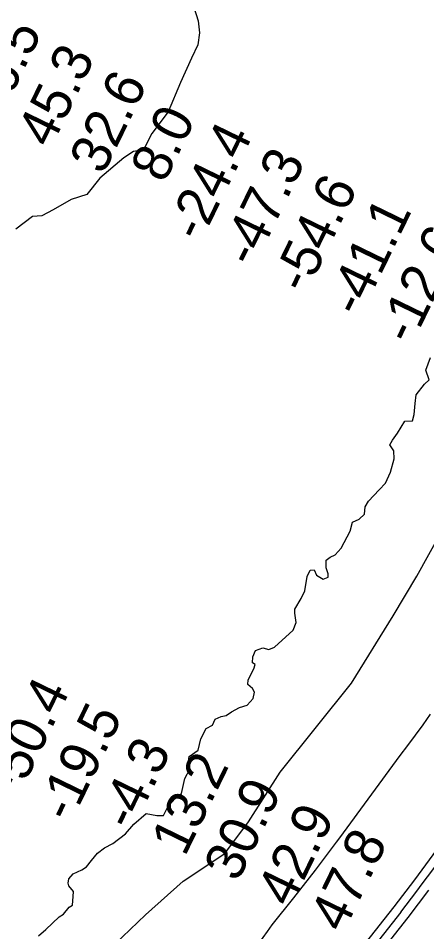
# Model space of a CAD drawing. Extents: x 3180038 to 3217926, y 922069 to 947485.
# Drawn here: x 3188541 to 3189237, y 935201 to 936760 of the extents above; entities that cross this region are included whole.
import ezdxf

# ---------------------------------------------------------------- set-up
doc = ezdxf.new("R2010")
doc.units = 0
for name, color, linetype in [('V-LEVE-TOET', 7, 'Continuous'), ('V-RIVR-EDGE', 7, 'Continuous'), ('V-RIVR-RANG', 7, 'Continuous'), ('V-ROAD-CNTR', 7, 'Continuous'), ('V-TOPO-SHOR', 7, 'Continuous')]:
    doc.layers.add(name, color=color, linetype=linetype)

msp = doc.modelspace()

# ---------------------------------------------------------------- linework, layer by layer
at = {"layer": 'V-LEVE-TOET'}
msp.add_lwpolyline([(3188950.6, 935180.6), (3188965.4, 935201.4), (3188973.1, 935212.6), (3188973.1, 935212.6), (3189010.5, 935259), (3189047.1, 935306), (3189082.9, 935353.6), (3189088.6, 935361.3), (3189088.6, 935361.3), (3189191.3, 935501.6), (3189191.3, 935501.6), (3189204.7, 935519), (3189217.8, 935536.5), (3189230.6, 935554.3), (3189243.1, 935572.3)], dxfattribs=at)
at = {"layer": 'V-RIVR-EDGE'}
for points in [[(3188839.8, 936778.5), (3188847, 936755.1)], [(3188847, 936755.1), (3188849.6, 936734.9), (3188846.4, 936714.7), (3188836, 936691.4), (3188817.2, 936649.9), (3188796.3, 936600.2), (3188768.2, 936562.9), (3188754.2, 936535), (3188737, 936532.4), (3188720.4, 936521.6), (3188679.4, 936486.9), (3188657.5, 936459), (3188630.5, 936450.7), (3188599.9, 936432.7), (3188580.7, 936422.8), (3188565.1, 936421.3), (3188536.5, 936399.6)], [(3188758.4, 935402.5), (3188776.5, 935399.4), (3188788.4, 935399.3), (3188796.3, 935415.4), (3188808.2, 935428.3), (3188819.1, 935437.1), (3188824.4, 935462.5), (3188833.2, 935478.1), (3188830.1, 935488.4), (3188831.7, 935499.9), (3188847.3, 935510.7), (3188852, 935529.9), (3188860.9, 935547.5), (3188871.8, 935553.2), (3188876, 935563.5), (3188886.4, 935568.2), (3188895.2, 935569.7), (3188904, 935576.4), (3188917.5, 935583.7), (3188930.5, 935587.8), (3188940.9, 935599.2), (3188943.5, 935610), (3188939.9, 935616.3), (3188931.6, 935623), (3188932.2, 935630.8), (3188942.1, 935649.5), (3188944.1, 935656.7), (3188940, 935659.8), (3188940.5, 935670.2), (3188944.7, 935680.6), (3188957.2, 935685.2), (3188967.5, 935682.6), (3188977.4, 935686.7), (3189009.1, 935715.7), (3189014.3, 935728.6), (3189011.8, 935744.7), (3189011.8, 935751.5), (3189022.7, 935769.6), (3189029, 935782.5), (3189033.2, 935806.9), (3189038.4, 935817.8), (3189045.2, 935818.8), (3189048.8, 935809.5), (3189060.2, 935802.7), (3189069, 935805.8), (3189069, 935811.5), (3189065.4, 935821.9), (3189065.4, 935835.3), (3189072.2, 935840), (3189081, 935844.1), (3189090.9, 935855.5), (3189106.5, 935884.5), (3189110.2, 935900.1), (3189121.6, 935905.2), (3189131, 935913.5), (3189132, 935925.9), (3189137.8, 935935.8), (3189146.6, 935945.6), (3189156, 935954.9), (3189166.4, 935966.3), (3189175.2, 935985), (3189181.5, 936007.8), (3189180.5, 936021.8), (3189173.8, 936031.6), (3189178.5, 936039.9), (3189186.8, 936051.8), (3189199.3, 936072), (3189212.3, 936073), (3189215.4, 936083.4), (3189217, 936102.6), (3189218.6, 936117.1), (3189233.2, 936135.2), (3189241, 936143), (3189235.3, 936159.1), (3189243.1, 936180.8)], [(3188575.3, 935194), (3188587.8, 935204.8), (3188610.1, 935226.6), (3188617.9, 935231.2), (3188627.3, 935243.1), (3188633, 935246.2), (3188634.1, 935261.3), (3188634.6, 935269.6), (3188626.8, 935279.4), (3188625.8, 935284.1), (3188626.9, 935291.4), (3188634.2, 935299.6), (3188648.7, 935306.3), (3188657, 935311.5), (3188665.3, 935322.4), (3188675.7, 935334.8), (3188687.7, 935344.1), (3188701.7, 935351.8), (3188723.5, 935367.9), (3188737.6, 935384.4), (3188758.4, 935402.5)]]:
    msp.add_lwpolyline(points, dxfattribs=at)
at = {"layer": 'V-ROAD-CNTR'}
for points in [[(3191151.8, 939057.1), (3189829.7, 936317.7), (3189780.6, 936216.3), (3189729.6, 936116.7), (3189676.7, 936017.8), (3189622.4, 935919), (3189566.1, 935821.9), (3189508.3, 935726.2), (3189454.5, 935639.5), (3189409.3, 935567.6), (3189362.7, 935497.1), (3189314.9, 935427.3), (3189266, 935357.7), (3189215.7, 935289.5), (3189180.7, 935243.5), (3188970.6, 934976.4)], [(3189239.7, 935271.6), (3189204.5, 935225.2), (3188985.5, 934946.7)], [(3189192.6, 935234.3), (3188973.6, 934955.8)]]:
    msp.add_lwpolyline(points, dxfattribs=at)
msp.add_arc((3185329.5, 938198.4), 4869.2, 322.5019, 328.187, dxfattribs=at)
at = {"layer": 'V-TOPO-SHOR'}
msp.add_lwpolyline([(3188341.8, 934753.7), (3188666.1, 935142.1), (3188757.3, 935230), (3188821.5, 935287.4), (3188892.4, 935334.7), (3188933, 935388.7), (3188987, 935473.2), (3189108.6, 935625.2), (3189179.6, 935740), (3189220.1, 935807.6), (3189260.6, 935881.9), (3189277.5, 935929.2), (3189297.8, 935986.6), (3189345.1, 936121.7), (3189493.7, 936331.2), (3189730.2, 936824.4)], dxfattribs=at)

# ---------------------------------------------------------------- texts
at = {"layer": 'V-RIVR-RANG'}
for s, p in [('46.5', (3188505.9, 936579.6)), ('45.3', (3188595.9, 936536.1)), ('32.6', (3188685.2, 936491)), ('8.0', (3188789.3, 936476.4)), ('-24.4', (3188851.5, 936375.8)), ('-47.3', (3188941.6, 936332.3)), ('-54.6', (3189030.8, 936287.1)), ('-41.1', (3189122.7, 936247.4)), ('-12.6', (3189210.9, 936200.1)), ('-50.4', (3188539.9, 935428.3)), ('-19.5', (3188629.9, 935384.8)), ('-4.3', (3188734.5, 935371.2)), ('13.2', (3188824.5, 935327.7)), ('30.9', (3188914.4, 935283.9)), ('42.9', (3189004.5, 935240.4)), ('47.8', (3189094.6, 935197.2))]:
    msp.add_text(s, height=67, rotation=64.0783, dxfattribs=at).set_placement(p)

doc.saveas('drawing.dxf')
